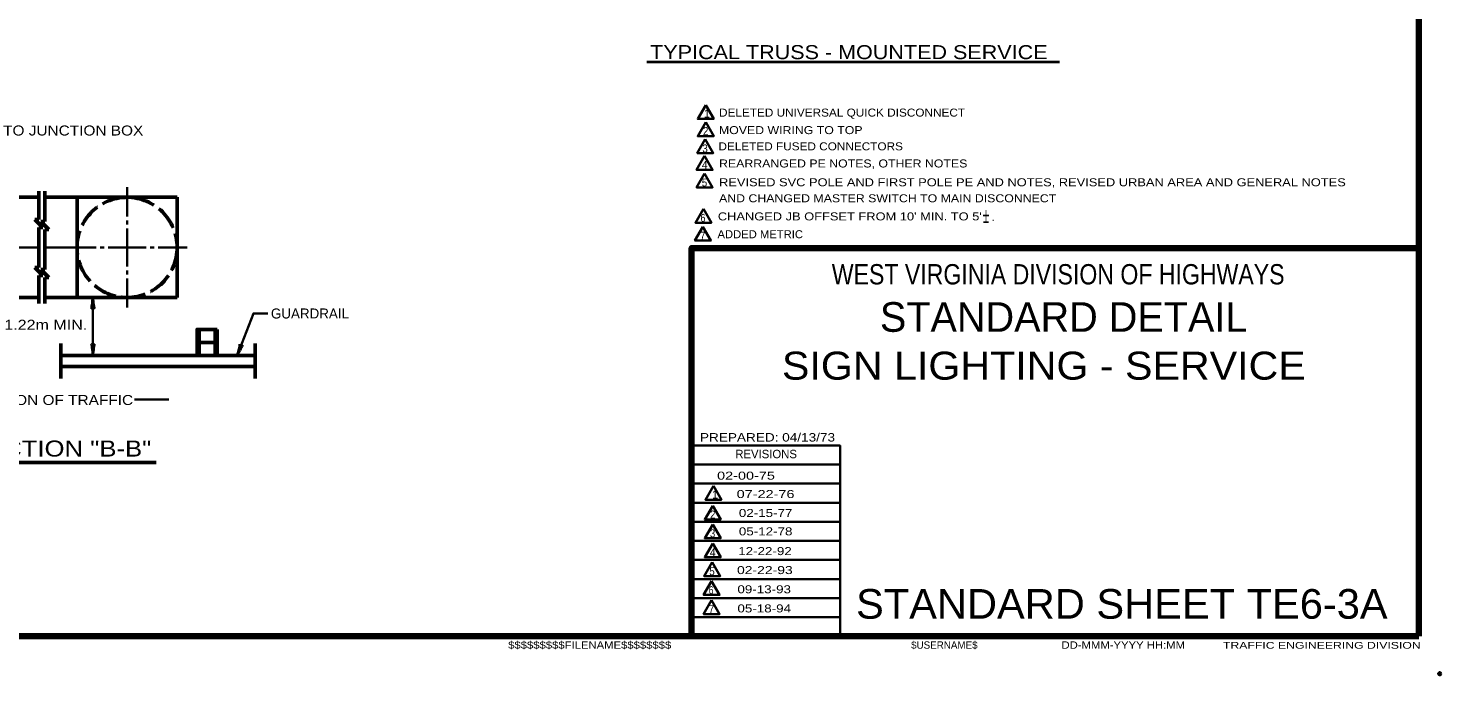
# Model space of a CAD drawing. Extents: x -111 to 744, y -77 to 467.
# Drawn here: x 320.8 to 744.3, y -77.4 to 116.4 of the extents above; entities that cross this region are included whole.
import ezdxf
from ezdxf.enums import TextEntityAlignment as Align

# ---------------------------------------------------------------- set-up
doc = ezdxf.new("R2010")
doc.units = 0
doc.header["$LTSCALE"] = 1.2
doc.header["$PDMODE"] = 32
doc.header["$PDSIZE"] = 0.6
doc.linetypes.add('LONG_DASHED', pattern=[7.5, 6, -1.5])
doc.layers.add('1', color=7, linetype='Continuous', lineweight=53)
doc.layers.add('61', color=7, linetype='Continuous', lineweight=35)

msp = doc.modelspace()

# ---------------------------------------------------------------- linework, layer by layer
at = {"layer": '1', "lineweight": 158}
for q in [(737.728, 460.265), (737.728, 50.465), (-53.872, -65.835)]:
    msp.add_line((737.728, -65.835), q, dxfattribs=at)
at = {"layer": '1', "lineweight": 13}
msp.add_line((737.728, -65.835), (737.728, 460.265), dxfattribs=at)
at = {"layer": '1', "lineweight": 40}
msp.add_line((506.299, 106.329), (629.982, 106.329), dxfattribs=at)
at = {"layer": '1', "lineweight": 35}
for p, q in [((350.465, 68.675), (350.465, 65.675)), ((350.465, 65.675), (350.465, 59.975)), ((350.465, 58.775), (350.465, 57.575)), ((350.465, 56.375), (350.465, 50.675)), ((314.465, 50.675), (324.065, 50.675)), ((335.465, 50.675), (325.865, 50.675)), ((341.165, 50.675), (335.465, 50.675)), ((343.565, 50.675), (342.365, 50.675)), ((350.465, 50.675), (344.765, 50.675)), ((358.565, 50.675), (357.365, 50.675)), ((365.465, 50.675), (359.765, 50.675)), ((368.465, 50.675), (365.465, 50.675)), ((350.465, 43.775), (350.465, 42.575)), ((350.465, 41.375), (350.465, 35.675)), ((340.216, 35.675), (340.216, 18.275)), ((350.465, 35.675), (350.465, 32.675)), ((352.672, 5.067), (363.041, 5.067)), ((564.228, -14.435), (519.728, -14.435)), ((564.228, -20.135), (519.728, -20.135)), ((564.228, -25.935), (519.728, -25.935)), ((564.228, -31.635), (519.728, -31.635)), ((564.228, -37.335), (519.728, -37.335)), ((564.228, -43.035), (519.728, -43.035)), ((564.228, -48.735), (519.728, -48.735)), ((564.228, -54.435), (519.728, -54.435)), ((564.228, -60.135), (519.728, -60.135))]:
    msp.add_line(p, q, dxfattribs=at)
at = {"layer": '1'}
for p, q in [((284.465, 65.675), (324.065, 65.675)), ((324.065, 67.475), (324.065, 59.075)), ((325.865, 67.475), (325.865, 58.475)), ((365.465, 65.675), (325.865, 65.675)), ((335.465, 65.675), (335.465, 35.675)), ((365.465, 65.675), (365.465, 35.675)), ((322.865, 59.075), (324.065, 59.075)), ((322.865, 59.075), (325.265, 56.675)), ((324.065, 56.675), (325.265, 56.675)), ((324.065, 56.675), (324.065, 44.675)), ((324.665, 58.475), (327.065, 56.075)), ((324.665, 58.475), (325.865, 58.475)), ((325.865, 56.075), (325.865, 44.075)), ((325.865, 56.075), (327.065, 56.075)), ((322.865, 44.675), (324.065, 44.675)), ((322.865, 44.675), (325.265, 42.275)), ((324.665, 44.075), (325.865, 44.075)), ((324.665, 44.075), (327.065, 41.675)), ((324.065, 42.275), (325.265, 42.275)), ((324.065, 42.275), (324.065, 33.875)), ((325.865, 41.675), (325.865, 33.875)), ((325.865, 41.675), (327.065, 41.675)), ((284.465, 35.675), (324.065, 35.675)), ((365.465, 35.675), (325.865, 35.675)), ((372.065, 18.275), (372.065, 26.075)), ((376.865, 18.275), (376.865, 26.075)), ((377.465, 18.275), (377.465, 26.075)), ((330.665, 21.875), (330.665, 11.375)), ((372.065, 22.175), (376.865, 22.175)), ((388.865, 21.875), (388.865, 11.375)), ((388.865, 18.275), (330.665, 18.275)), ((388.865, 14.975), (330.665, 14.975)), ((301.229, -13.857), (359.176, -13.857))]:
    msp.add_line(p, q, dxfattribs=at)
at = {"layer": '1', "lineweight": 35}
for points in [[(523.953, 93.343), (521.553, 89.186), (526.353, 89.186)], [(523.953, 88.163), (521.553, 84.006), (526.353, 84.006)], [(523.837, 83.102), (521.437, 78.945), (526.237, 78.945)], [(523.639, 78.066), (521.239, 73.909), (526.039, 73.909)], [(523.639, 72.799), (521.239, 68.642), (526.039, 68.642)], [(523.27, 62.196), (520.87, 58.039), (525.67, 58.039)], [(523.113, 56.852), (520.713, 52.695), (525.513, 52.695)], [(526.253, -20.823), (523.853, -24.98), (528.653, -24.98)], [(526.061, -26.767), (523.661, -30.924), (528.461, -30.924)], [(526.061, -32.363), (523.661, -36.52), (528.461, -36.52)], [(526.061, -38.05), (523.661, -42.207), (528.461, -42.207)], [(525.892, -43.724), (523.492, -47.881), (528.292, -47.881)], [(525.712, -49.371), (523.312, -53.528), (528.112, -53.528)], [(525.712, -55.108), (523.312, -59.265), (528.112, -59.265)]]:
    msp.add_lwpolyline(points, close=True, dxfattribs=at)
for points in [[(356.165, 50.675), (350.465, 50.675), (350.465, 44.975)], [(383.517, 18.275), (388.368, 30.892), (392.711, 30.892)], [(564.228, -65.835), (564.228, -8.735), (519.728, -8.735)]]:
    msp.add_lwpolyline(points, dxfattribs=at)
at = {"layer": '1', "lineweight": 158}
msp.add_lwpolyline([(519.728, -65.835), (519.728, 50.465), (737.728, 50.465)], dxfattribs=at)
at = {"layer": '1'}
msp.add_lwpolyline([(371.465, 18.275), (371.465, 26.075), (377.465, 26.075)], dxfattribs=at)
at = {"layer": '1', "linetype": 'LONG_DASHED'}
msp.add_circle((350.465, 50.675), 15, dxfattribs=at)
at = {"layer": '1', "lineweight": 40}
for centre, major_axis, ratio, start_param, end_param in [((339.962, 34.331), (0.211, 2.108), 0.07063, 3.1407148, 5.41811), ((339.962, 34.331), (0.211, 2.108), 0.07063, 3.1407148, 5.41811), ((340.548, 34.366), (-0.187, 2.143), 0.122415, 0.8963533, 3.1415927), ((340.548, 34.366), (-0.187, 2.143), 0.122415, 0.8963533, 3.1415927), ((339.894, 19.596), (0.187, -2.143), 0.122415, 0.8963533, 3.1415927), ((340.48, 19.631), (-0.211, -2.108), 0.07063, 3.1407148, 5.41811), ((383.677, 19.617), (-0.594, -2.067), 0.122415, 0.8963533, 3.1415927), ((383.677, 19.617), (-0.594, -2.067), 0.122415, 0.8963533, 3.1415927), ((384.236, 19.439), (-0.953, -1.892), 0.07063, 3.1407148, 5.41811), ((384.236, 19.439), (-0.953, -1.892), 0.07063, 3.1407148, 5.41811)]:
    msp.add_ellipse(centre, major_axis=major_axis, ratio=ratio, start_param=start_param, end_param=end_param, dxfattribs=at)
at = {"layer": '1'}
msp.add_point((744.028, -77.135), dxfattribs=at)
at = {"layer": '61', "lineweight": 53}
for q in [(585.028, -65.835), (585.028, -65.835), (585.028, -65.835), (585.328, -65.835), (585.328, -65.835)]:
    msp.add_line((737.728, -65.835), q, dxfattribs=at)

# ---------------------------------------------------------------- texts
at = {"layer": '1'}
for s, height, width, p in [('TYPICAL TRUSS - MOUNTED SERVICE', 4.2, 1.15, (507.302, 107.094)), ('DELETED UNIVERSAL QUICK DISCONNECT', 2.4, 1.1, (527.95, 89.873)), ('2', 2.4, 0.9, (523.136, 84.344)), ('MOVED WIRING TO TOP', 2.4, 1.15, (527.925, 84.625)), ('3', 2.4, 0.9, (522.958, 79.121)), ('DELETED FUSED CONNECTORS', 2.4, 1.1, (527.772, 79.758)), ('4', 2.4, 0.95, (522.79, 74.175)), ('REARRANGED PE NOTES, OTHER NOTES', 2.4, 1.15, (527.958, 74.627)), ('5', 2.4, 0.9, (522.79, 68.908)), ('REVISED SVC POLE AND FIRST POLE PE AND NOTES, REVISED URBAN AREA AND GENERAL NOTES', 2.4, 1.2, (527.958, 68.986)), ('AND CHANGED MASTER SWITCH TO MAIN DISCONNECT', 2.4, 1.15, (527.958, 64.186)), ('6', 2.4, 0.8, (522.421, 58.305)), ("CHANGED JB OFFSET FROM 10' MIN. TO 5'", 2.4, 1.2, (527.589, 58.757)), ('7', 2.4, 0.9, (522.264, 52.961)), ('ADDED METRIC', 2.4, 1.05, (527.479, 53.407)), ('PREPARED: 04/13/73', 2.537, 1.2, (522.228, -7.535)), ('2', 2.4, 0.9, (525.248, -30.623)), ('3', 2.4, 0.9, (525.212, -36.254)), ('4', 2.4, 0.95, (525.212, -41.941)), ('5', 2.4, 0.9, (525.042, -47.615)), ('6', 2.4, 0.8, (524.862, -53.261)), ('STANDARD SHEET TE6-3A', 8.881, 1.05, (569.028, -60.635)), ('7', 2.4, 0.9, (524.862, -58.998)), ('$$$$$$$$$FILENAME$$$$$$$$', 2.2, 1.15, (464.728, -69.635)), ('DD-MMM-YYYY HH:MM', 2.2, 1.15, (630.628, -69.635)), ('TRAFFIC ENGINEERING DIVISION', 2.031, 1.35, (679.028, -69.635))]:
    msp.add_text(s, height=height, dxfattribs=dict(at, width=width)).set_placement(p)
for s, height, p in [('1', 2.4, (523.446, 89.592)), ('REVISIONS', 2.537, (532.828, -12.535)), ('1', 2.4, (525.872, -24.616)), ('$USERNAME$', 2.2, (585.528, -69.635))]:
    msp.add_text(s, height=height, dxfattribs=at).set_placement(p)
for s, height, width, p in [('TO JUNCTION BOX', 3, 1.15, (334.321, 84.204)), ('+', 4.8, 0.55, (607.986, 57.86)), ('WEST VIRGINIA DIVISION OF HIGHWAYS', 6.089, 0.85, (629.628, 39.565)), ('1.22m MIN.', 3, 1.2, (326.103, 25.959)), ('SIGN LIGHTING - SERVICE', 8.391, 1.1, (625.331, 11.018)), ('DIRECTION OF TRAFFIC', 3, 1.15, (325.374, 3.423)), ('SECTION "B-B"', 4.8, 1.2, (330.39, -12.032)), ('02-00-75', 2.4, 1.35, (536.031, -18.954)), ('07-22-76', 2.4, 1.35, (541.9, -24.47)), ('02-15-77', 2.4, 1.25, (541.924, -30.142)), ('05-12-78', 2.4, 1.25, (541.924, -35.658)), ('12-22-92', 2.4, 1.25, (541.732, -41.571)), ('02-22-93', 2.4, 1.3, (541.688, -47.262)), ('09-13-93', 2.4, 1.25, (541.49, -53.017)), ('05-18-94', 2.4, 1.25, (541.499, -58.754))]:
    msp.add_text(s, height=height, dxfattribs=dict(at, width=width)).set_placement(p, align=Align.CENTER)
for s, height, p in [('-', 4.8, (607.997, 56.355)), ('.', 2.4, (610.123, 58.589)), ('STANDARD DETAIL', 8.881, (631.278, 25.365)), ('GUARDRAIL', 3, (405.305, 29.352))]:
    msp.add_text(s, height=height, dxfattribs=at).set_placement(p, align=Align.CENTER)

doc.saveas('drawing.dxf')
